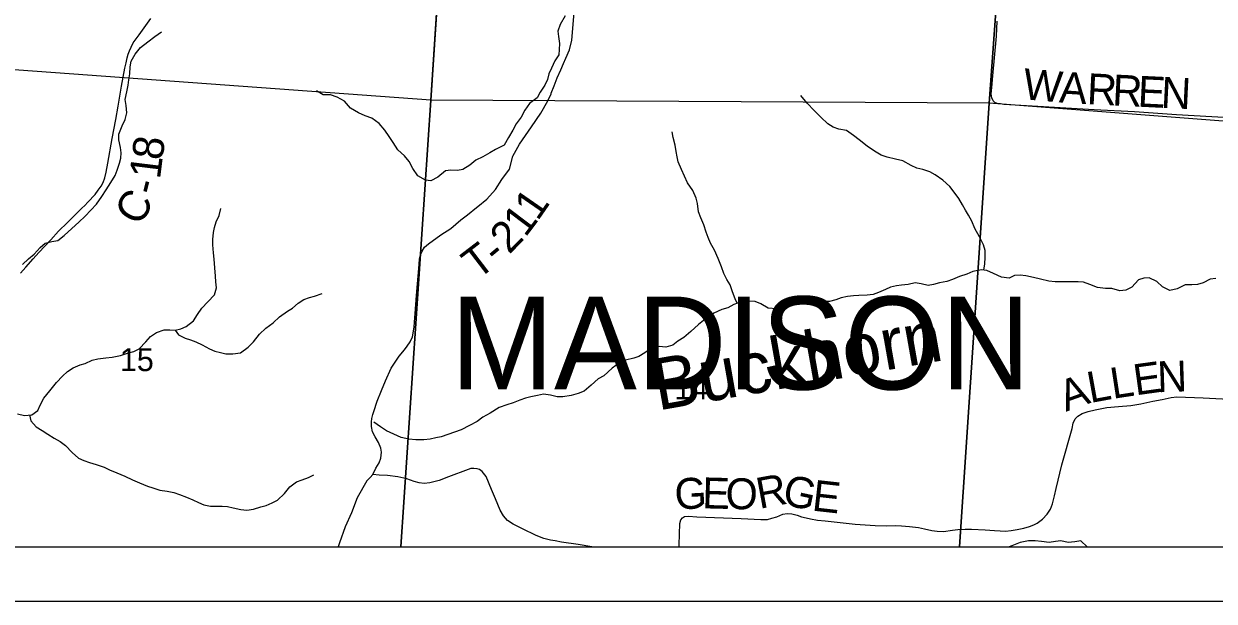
# Model space of a CAD drawing. Extents: x 0 to 40.8, y 0 to 22.
# Drawn here: x 5.517 to 7.699, y 14 to 15.059 of the extents above; entities that cross this region are included whole.
import ezdxf

# ---------------------------------------------------------------- set-up
doc = ezdxf.new("R2010")
doc.units = 0
for name, color, linetype in [('Default', 7, 'Continuous'), ('GM_X_County_Road', 7, 'Continuous'), ('GM_X_County_Road_Text', 7, 'Continuous'), ('GM_X_Minor_River', 7, 'Continuous'), ('GM_X_Minor_River_Text', 7, 'Continuous'), ('GM_X_Section', 7, 'Continuous'), ('GM_X_Section_Text', 7, 'Continuous'), ('GM_X_Township_Road', 7, 'Continuous'), ('GM_X_Township_Road_Text', 7, 'Continuous'), ('GM_X_Township_Text', 7, 'Continuous'), ('SH_Cut_Line', 7, 'Continuous'), ('SH_Data', 7, 'Continuous')]:
    doc.layers.add(name, color=color, linetype=linetype)

msp = doc.modelspace()

# ---------------------------------------------------------------- linework, layer by layer
at = {"layer": 'Default'}
msp.add_lwpolyline([(2.1, 16.4387), (2.1, 14.1), (8.9, 14.1), (8.9, 16.9831), (7.7161, 17.0658), (7.7144, 17.066), (7.54, 17.0745), (7.4495, 17.0841), (6.9172, 17.1197), (6.1785, 17.166), (5.6278, 17.197), (5.3407, 17.2146), (4.8294, 17.2493), (4.5348, 17.2687), (3.4481, 17.3334), (3.1244, 17.3534), (2.8484, 17.3691), (2.8463, 17.3693), (2.4594, 17.3966), (2.4379, 17.0913), (2.3911, 16.4258)], close=True, dxfattribs=at)
at = {"layer": 'GM_X_County_Road'}
for points in [[(5.511, 14.6017), (5.5206, 14.6128), (5.5339, 14.6281), (5.5443, 14.6398), (5.5662, 14.6632), (5.5807, 14.6792), (5.5969, 14.695), (5.6142, 14.7123), (5.6234, 14.7209), (5.6287, 14.726), (5.6341, 14.7319), (5.6478, 14.7461), (5.6534, 14.754), (5.6587, 14.7614), (5.6623, 14.7685), (5.6653, 14.7769), (5.6676, 14.7871), (5.6709, 14.8036), (5.6788, 14.8491), (5.6854, 14.884), (5.69, 14.9081), (5.6961, 14.945), (5.7022, 14.9783), (5.7044, 14.9879), (5.7063, 14.9971), (5.7083, 15.004), (5.7106, 15.0098), (5.7139, 15.0167), (5.7177, 15.0243), (5.7228, 15.0317), (5.7287, 15.0393), (5.7498, 15.0691)], [(6.5583, 14.1), (6.5333, 14.1041), (6.5028, 14.1081), (6.4909, 14.1105), (6.4827, 14.112), (6.4703, 14.1152), (6.4562, 14.1208), (6.4315, 14.133), (6.4141, 14.1412), (6.4037, 14.1481), (6.3966, 14.1564), (6.3903, 14.1673), (6.3819, 14.1876), (6.3745, 14.2049), (6.3648, 14.2286), (6.3572, 14.238), (6.3527, 14.2417), (6.3479, 14.243), (6.3423, 14.2438), (6.3367, 14.2433), (6.3315, 14.2419), (6.2956, 14.2285), (6.2787, 14.2216), (6.2612, 14.2171), (6.2507, 14.2158), (6.2415, 14.217), (6.2326, 14.2194), (6.2191, 14.2245), (6.2024, 14.2285), (6.1835, 14.2305), (6.1686, 14.231), (6.1566, 14.2328), (6.1519, 14.227), (6.1459, 14.2209), (6.128, 14.1896), (6.1175, 14.1624), (6.106, 14.1363), (6.0956, 14.1074), (6.093, 14.1)]]:
    msp.add_lwpolyline(points, dxfattribs=at)
for points in [[(5.1921, 14.1), (6.208, 14.1), (6.2633, 14.9194), (5.2555, 14.9926)], [(6.208, 14.1), (7.2324, 14.1), (7.2868, 14.9136), (6.2633, 14.9194)], [(7.2324, 14.1), (8.213, 14.1), (8.2617, 14.8595), (7.7715, 14.8766), (7.2868, 14.9136)]]:
    msp.add_lwpolyline(points, close=True, dxfattribs=at)
at = {"layer": 'GM_X_Minor_River'}
for points in [[(6.5093, 15.0742), (6.5001, 15.0582), (6.4959, 15.0457), (6.4974, 15.0362), (6.4989, 15.0233), (6.4985, 15.0123), (6.4978, 15.0028), (6.4905, 14.9915), (6.4845, 14.9778), (6.4795, 14.9676), (6.4772, 14.9573), (6.4723, 14.9467), (6.4636, 14.9342), (6.4582, 14.9236), (6.4442, 14.9134), (6.4358, 14.9009), (6.429, 14.8884), (6.4199, 14.8762), (6.4134, 14.8641), (6.4054, 14.8508), (6.3978, 14.8368), (6.3819, 14.8289), (6.3713, 14.8228), (6.3588, 14.8152), (6.3459, 14.8092), (6.3349, 14.8001), (6.322, 14.7922), (6.3118, 14.7903), (6.2996, 14.7907), (6.2902, 14.7895), (6.2761, 14.7778), (6.2632, 14.7714), (6.2534, 14.7725), (6.2394, 14.7805), (6.2299, 14.7942), (6.2235, 14.8067), (6.2152, 14.8174), (6.2027, 14.828), (6.1944, 14.8417), (6.1868, 14.8527), (6.1789, 14.8645), (6.1683, 14.8766), (6.1547, 14.8862), (6.143, 14.8903), (6.1305, 14.8964), (6.1161, 14.9044), (6.1047, 14.9177), (6.0915, 14.925), (6.0794, 14.9292), (6.0657, 14.9292), (6.0536, 14.9364)], [(5.5144, 14.6177), (5.5257, 14.6283), (5.5356, 14.637), (5.5466, 14.6492), (5.556, 14.6571), (5.5682, 14.6598), (5.5792, 14.6621), (5.5909, 14.6708), (5.6049, 14.6841), (5.6178, 14.6954), (5.6292, 14.7064), (5.6398, 14.7178), (5.65, 14.7288), (5.6602, 14.7425), (5.6682, 14.755), (5.6765, 14.7683), (5.6841, 14.7812), (5.6883, 14.7911), (5.6925, 14.8036), (5.6947, 14.8131), (5.6955, 14.8229), (5.694, 14.8328), (5.691, 14.8465), (5.6913, 14.8567), (5.697, 14.8723), (5.7027, 14.884), (5.7057, 14.8958), (5.7046, 14.9098), (5.7027, 14.9208), (5.7057, 14.9349), (5.7084, 14.947), (5.7095, 14.9565), (5.7111, 14.9675), (5.7122, 14.9804), (5.7137, 14.9906), (5.7209, 15.0035), (5.7311, 15.016), (5.744, 15.0263), (5.7569, 15.0362), (5.7694, 15.0445)], [(7.2772, 14.6074), (7.2787, 14.6191), (7.2795, 14.6305), (7.2795, 14.6434), (7.2768, 14.6536), (7.2693, 14.6684), (7.2606, 14.684), (7.2553, 14.6973), (7.2489, 14.7083), (7.2432, 14.7178), (7.2379, 14.7273), (7.2311, 14.7387), (7.2247, 14.7482), (7.2145, 14.7611), (7.202, 14.7725), (7.188, 14.7824), (7.1778, 14.7877), (7.1653, 14.7923), (7.154, 14.7946), (7.1441, 14.7995), (7.1286, 14.8079), (7.115, 14.811), (7.0998, 14.8148), (7.0888, 14.8186), (7.0767, 14.8255), (7.0635, 14.835), (7.0487, 14.8467), (7.0381, 14.8544), (7.0253, 14.8639), (7.0113, 14.8662), (7.001, 14.8696), (6.9912, 14.8761), (6.9783, 14.8882), (6.9662, 14.9004), (6.9534, 14.9141), (6.9417, 14.9277)], [(6.8248, 14.5466), (6.8209, 14.5546), (6.8164, 14.5678), (6.8119, 14.5807), (6.8062, 14.5902), (6.8005, 14.6013), (6.796, 14.6134), (6.79, 14.629), (6.7832, 14.6442), (6.776, 14.6571), (6.7719, 14.6673), (6.7677, 14.6772), (6.7636, 14.6905), (6.7583, 14.7034), (6.7538, 14.7144), (6.7523, 14.73), (6.7496, 14.7398), (6.7436, 14.7539), (6.7338, 14.7679), (6.7281, 14.7801), (6.7228, 14.7923), (6.7164, 14.8059), (6.7149, 14.8154), (6.713, 14.8249), (6.7112, 14.8367), (6.7078, 14.8507), (6.7055, 14.861)], [(5.5056, 14.3441), (5.5181, 14.3407), (5.5318, 14.3422), (5.5427, 14.3502), (5.5469, 14.3597), (5.5534, 14.3726), (5.5647, 14.3862), (5.5768, 14.401), (5.5878, 14.4128), (5.5973, 14.4215), (5.6075, 14.4283), (5.62, 14.4336), (5.6295, 14.4363), (5.6424, 14.442), (5.6526, 14.4446), (5.667, 14.4465), (5.6788, 14.4477), (5.6943, 14.4511), (5.7068, 14.4549), (5.7186, 14.4579), (5.7284, 14.4632), (5.7405, 14.4761), (5.7489, 14.4856), (5.7602, 14.4932), (5.7743, 14.4977), (5.7845, 14.4977), (5.7947, 14.4974), (5.8049, 14.5), (5.8148, 14.5042), (5.8281, 14.5144), (5.8353, 14.5258), (5.8432, 14.5379), (5.8542, 14.5493), (5.8663, 14.5622), (5.8701, 14.5747), (5.869, 14.5861), (5.8682, 14.5964), (5.8671, 14.6119), (5.866, 14.6279), (5.8648, 14.6393), (5.8637, 14.6541), (5.8637, 14.6635), (5.8648, 14.6764), (5.8667, 14.6859), (5.8694, 14.6958), (5.8751, 14.7079), (5.8781, 14.7205)], [(7.7026, 14.5919), (7.6923, 14.5911), (7.6791, 14.5843), (7.6688, 14.5809), (7.6582, 14.5805), (7.6465, 14.5806), (7.6313, 14.573), (7.618, 14.5704), (7.6048, 14.5768), (7.5946, 14.5867), (7.5802, 14.5932), (7.5707, 14.5928), (7.5609, 14.5898), (7.5487, 14.5765), (7.5377, 14.5705), (7.5264, 14.5694), (7.5116, 14.5736), (7.4999, 14.574), (7.4858, 14.5759), (7.4715, 14.5812), (7.4597, 14.5854), (7.4499, 14.5858), (7.4374, 14.5862), (7.4222, 14.5859), (7.4082, 14.5859), (7.3964, 14.5874), (7.3813, 14.5909), (7.3684, 14.5939), (7.3544, 14.597), (7.3438, 14.5985), (7.3336, 14.5974), (7.3233, 14.5928), (7.3093, 14.5944), (7.2949, 14.6012), (7.2828, 14.6066), (7.2726, 14.6081), (7.2571, 14.6051), (7.2461, 14.6002), (7.2328, 14.5956), (7.2199, 14.5903), (7.2093, 14.5866), (7.1957, 14.5839), (7.1847, 14.5809), (7.1748, 14.5794), (7.1623, 14.5821), (7.1513, 14.584), (7.1381, 14.5814), (7.1263, 14.5799), (7.1168, 14.5787), (7.1062, 14.5761), (7.0968, 14.5719), (7.0842, 14.5663), (7.074, 14.5629), (7.063, 14.5614), (7.0479, 14.561), (7.0384, 14.5603), (7.0274, 14.5592), (7.0153, 14.5565), (7.0058, 14.5527), (6.994, 14.5501), (6.9846, 14.5501), (6.9747, 14.5509), (6.9626, 14.552), (6.9524, 14.5517), (6.9425, 14.5513), (6.9281, 14.5506), (6.9187, 14.5483), (6.9084, 14.5434), (6.8967, 14.5366), (6.8815, 14.5374), (6.8683, 14.5454), (6.858, 14.5499), (6.8417, 14.5507), (6.8319, 14.5492), (6.8186, 14.5443), (6.8076, 14.5383), (6.797, 14.5352), (6.7822, 14.5284), (6.7727, 14.5216), (6.7633, 14.5152), (6.7538, 14.508), (6.7397, 14.4947), (6.7268, 14.4841), (6.7162, 14.4773), (6.7067, 14.4701), (6.6939, 14.466), (6.6821, 14.4675), (6.6688, 14.4656), (6.6556, 14.4558), (6.6446, 14.4493), (6.6351, 14.4459), (6.6203, 14.4422), (6.6089, 14.4373), (6.5957, 14.4274), (6.5805, 14.4138), (6.5699, 14.4081), (6.5573, 14.3964), (6.5441, 14.3854), (6.5331, 14.3812), (6.5202, 14.3774)], [(5.7947, 14.4974), (5.8008, 14.489), (5.8129, 14.4829), (5.8224, 14.4795), (5.8326, 14.4757), (5.844, 14.4704), (5.8572, 14.4628), (5.8674, 14.459), (5.8777, 14.4564), (5.8871, 14.4541), (5.9004, 14.4537), (5.914, 14.456), (5.9284, 14.4662), (5.9379, 14.4757), (5.9489, 14.4897), (5.9607, 14.5011), (5.9739, 14.5106), (5.986, 14.522), (6.0001, 14.5319), (6.0095, 14.5379), (6.0201, 14.547), (6.0304, 14.5535), (6.0406, 14.5573), (6.0501, 14.5595), (6.0637, 14.5649)], [(6.5202, 14.3774), (6.5054, 14.3748), (6.4948, 14.3752), (6.4827, 14.3783), (6.4698, 14.3798), (6.4588, 14.3775), (6.4467, 14.3753), (6.4365, 14.3723), (6.4262, 14.3689), (6.4141, 14.364), (6.4023, 14.3602), (6.3883, 14.3553), (6.372, 14.3451), (6.3587, 14.3375), (6.3481, 14.3299), (6.3341, 14.3227), (6.3189, 14.3144), (6.3064, 14.3103), (6.2943, 14.3057), (6.2821, 14.3019), (6.2723, 14.2997), (6.2617, 14.2974), (6.2503, 14.2963), (6.2359, 14.2963), (6.223, 14.2971), (6.209, 14.3002), (6.1954, 14.3063), (6.1821, 14.3127), (6.1708, 14.32), (6.1587, 14.3287)], [(5.5276, 14.3417), (5.5295, 14.3312), (5.5397, 14.3198), (5.5503, 14.313), (5.5609, 14.3065), (5.5727, 14.2989), (5.5833, 14.2932), (5.5935, 14.286), (5.6056, 14.2731), (5.6174, 14.2625), (5.6268, 14.2579), (5.6371, 14.2545), (5.6496, 14.2511), (5.664, 14.2458), (5.6742, 14.2412), (5.6875, 14.2356), (5.7019, 14.2295), (5.7159, 14.223), (5.7291, 14.2173), (5.7439, 14.2113), (5.7534, 14.2082), (5.7666, 14.2037), (5.7799, 14.2018), (5.792, 14.1995), (5.8022, 14.1961), (5.8151, 14.1911), (5.8269, 14.1862), (5.8371, 14.1813), (5.8469, 14.1767), (5.8591, 14.1741), (5.8701, 14.1741), (5.8803, 14.1741), (5.8905, 14.1737), (5.9007, 14.1714), (5.9151, 14.168), (5.9257, 14.1672), (5.9383, 14.1691), (5.9515, 14.1733), (5.961, 14.1759), (5.9724, 14.1805), (5.9818, 14.1854), (5.9947, 14.1979), (6.0046, 14.2101), (6.0171, 14.2192), (6.0273, 14.2226), (6.039, 14.2268), (6.0485, 14.2321)], [(7.4665, 14.1), (7.4547, 14.1107), (7.4441, 14.1092), (7.4316, 14.1077), (7.4184, 14.1108), (7.4085, 14.1093), (7.3971, 14.1078), (7.3827, 14.1093), (7.3714, 14.1105), (7.3593, 14.1105), (7.3437, 14.1079), (7.3282, 14.1018), (7.3237, 14.1)]]:
    msp.add_lwpolyline(points, dxfattribs=at)
at = {"layer": 'GM_X_Section'}
for points in [[(6.3112, 15.6512), (6.2633, 14.9194), (5.2555, 14.9926), (5.3264, 16.0026), (5.5999, 15.9856)], [(7.079, 15.9397), (7.3612, 15.9396), (7.2868, 14.9136), (6.2633, 14.9194), (6.311, 15.6491)]]:
    msp.add_lwpolyline(points, dxfattribs=at)
msp.add_lwpolyline([(8.344, 15.8695), (8.2661, 14.9102), (8.2617, 14.8595), (7.7715, 14.8766), (7.2868, 14.9136), (7.3612, 15.9396)], close=True, dxfattribs=at)
at = {"layer": 'GM_X_Township_Road'}
for points in [[(6.4841, 14.9319), (6.4894, 14.9455), (6.495, 14.9605), (6.5013, 14.9753), (6.5064, 14.9864), (6.5105, 14.9966), (6.5173, 15.0119), (6.5217, 15.0297), (6.5255, 15.0727), (6.5308, 15.122), (6.5364, 15.1668), (6.5377, 15.178)], [(7.7276, 14.8872), (7.6304, 14.8923), (7.5534, 14.8977), (7.4796, 14.9017), (7.314, 14.9116), (7.3074, 14.9124), (7.3016, 14.9134), (7.297, 14.9149), (7.2942, 14.918), (7.2919, 14.9236), (7.2906, 14.9305), (7.2922, 14.9495), (7.2939, 14.9643), (7.3003, 15.037), (7.3013, 15.0642)], [(6.3472, 14.7224), (6.3495, 14.7242), (6.3658, 14.738), (6.3818, 14.7555), (6.3935, 14.7737), (6.4072, 14.7929), (6.4138, 14.8168), (6.4255, 14.8389), (6.4479, 14.8702), (6.4647, 14.8957), (6.4779, 14.9183), (6.4838, 14.931), (6.4841, 14.9319)], [(6.1566, 14.2328), (6.1625, 14.2439), (6.1687, 14.2537), (6.1717, 14.2624), (6.1727, 14.2733), (6.1712, 14.281), (6.1671, 14.2911), (6.161, 14.3016), (6.1565, 14.3107), (6.1542, 14.3204), (6.1542, 14.3293), (6.1547, 14.3354), (6.157, 14.3428), (6.1585, 14.3478), (6.1648, 14.3669), (6.1727, 14.3864), (6.1798, 14.4046), (6.1902, 14.4278), (6.2053, 14.4496), (6.2152, 14.4613), (6.2198, 14.4679), (6.2251, 14.4758), (6.2297, 14.4852), (6.2307, 14.492), (6.2327, 14.5035), (6.2368, 14.5612), (6.2416, 14.6179), (6.2427, 14.6281), (6.2444, 14.6357), (6.2474, 14.6424), (6.2518, 14.6495), (6.2589, 14.6558), (6.2813, 14.6721), (6.2999, 14.6841), (6.3182, 14.6996), (6.3302, 14.7092), (6.3472, 14.7224)], [(6.7184, 14.1), (6.7185, 14.1036), (6.7199, 14.1426), (6.7217, 14.1492), (6.7245, 14.1527), (6.7283, 14.1555), (6.7354, 14.1563), (6.7507, 14.1548), (6.8321, 14.1515), (6.8682, 14.1497), (6.8802, 14.1502), (6.8886, 14.1522), (6.8975, 14.155), (6.9084, 14.1596), (6.9168, 14.1611), (6.9252, 14.1601), (6.9346, 14.1576), (6.9427, 14.1548), (6.9514, 14.1527), (6.959, 14.151), (6.9722, 14.1489), (6.986, 14.1476), (7.0409, 14.1413), (7.078, 14.139), (7.0981, 14.1382), (7.1149, 14.1387), (7.1261, 14.1385), (7.1411, 14.1372), (7.1576, 14.1354), (7.1681, 14.1329), (7.1815, 14.1296), (7.1915, 14.1283), (7.2029, 14.1281), (7.2197, 14.1301), (7.2296, 14.1316), (7.2426, 14.1324), (7.2543, 14.1319), (7.2797, 14.1311), (7.2965, 14.1298), (7.3069, 14.1293), (7.3171, 14.1288), (7.3273, 14.1298), (7.3385, 14.1316), (7.3502, 14.1339), (7.3606, 14.137), (7.3687, 14.14), (7.3748, 14.1433), (7.3845, 14.1504), (7.3934, 14.1596), (7.3995, 14.1688), (7.4031, 14.1789), (7.4066, 14.1934), (7.4097, 14.2066), (7.4203, 14.2501), (7.4389, 14.3168), (7.4412, 14.3269), (7.4448, 14.3346), (7.4493, 14.3394), (7.4572, 14.3442), (7.4682, 14.3483), (7.4814, 14.3511), (7.5025, 14.3554), (7.5239, 14.357), (7.5465, 14.359), (7.5648, 14.362), (7.5867, 14.3671), (7.6042, 14.3704), (7.6208, 14.374), (7.6309, 14.375), (7.6793, 14.3732), (7.738, 14.3699)]]:
    msp.add_lwpolyline(points, dxfattribs=at)
at = {"layer": 'SH_Cut_Line'}
msp.add_lwpolyline([(2.1, 17.4153), (2.1, 14.1), (8.9, 14.1), (8.9, 16.9831), (7.7161, 17.0658), (7.7144, 17.066), (7.54, 17.0745), (7.4495, 17.0841), (6.9172, 17.1197), (6.1785, 17.166), (5.6278, 17.197), (5.3407, 17.2146), (4.8294, 17.2493), (4.5348, 17.2687), (3.4481, 17.3334), (3.1244, 17.3534), (2.8484, 17.3691), (2.8463, 17.3693), (2.4594, 17.3966)], close=True, dxfattribs=at)
at = {"layer": 'SH_Data'}
for p, q in [((2.1, 14.1), (8.9, 14.1)), ((2, 14), (9, 14))]:
    msp.add_line(p, q, dxfattribs=at)

# ---------------------------------------------------------------- texts
at = {"layer": 'GM_X_County_Road_Text'}
for s, rotation, p in [('8', 82.558, (5.7709, 14.8077)), ('1', 83.0003, (5.7666, 14.7731)), ('-', 76.2276, (5.7597, 14.7432)), ('C', 59.3803, (5.7291, 14.6862))]:
    msp.add_text(s, height=0.0568, rotation=rotation, dxfattribs=at).set_placement(p)
at = {"layer": 'GM_X_Minor_River_Text'}
msp.add_text('Buckhorn', height=0.09469, rotation=10.0043, dxfattribs=at).set_placement((6.6792, 14.3496))
at = {"layer": 'GM_X_Section_Text'}
for s, p in [('15', (5.693, 14.4222)), ('14', (6.7096, 14.3703))]:
    msp.add_text(s, height=0.04186, rotation=0, dxfattribs=at).set_placement(p)
at = {"layer": 'GM_X_Township_Road_Text'}
for s, rotation, p in [('W', 354.8832, (7.3472, 14.9213)), ('A', 356.3069, (7.4143, 14.9153)), ('R', 357.2005, (7.4652, 14.9121)), ('R', 357.2413, (7.5118, 14.9098)), ('E', 357.2457, (7.5584, 14.9075)), ('N', 357.2413, (7.6009, 14.9055)), ('1', 55.3287, (6.459, 14.6962)), ('1', 52.8735, (6.4364, 14.6662)), ('2', 45.5826, (6.4067, 14.6352)), ('T', 37.469, (6.3485, 14.5886)), ('-', 39.8125, (6.3842, 14.6161)), ('L', 8.6944, (7.5135, 14.3712)), ('E', 7.8677, (7.5553, 14.3776)), ('N', 1.9164, (7.5958, 14.3833)), ('A', 19.7114, (7.4274, 14.3474)), ('L', 10.3324, (7.4721, 14.3636)), ('R', 10.4651, (6.8656, 14.1693)), ('G', 347.937, (6.9056, 14.1779)), ('G', 3.0505, (6.7115, 14.1679)), ('E', 358.5213, (6.7603, 14.1705)), ('O', 358.7388, (6.803, 14.1694)), ('E', 353.6141, (6.9606, 14.1665))]:
    msp.add_text(s, height=0.0568, rotation=rotation, dxfattribs=at).set_placement(p)
at = {"layer": 'GM_X_Township_Text'}
msp.add_text('MADISON', height=0.17045, rotation=0, dxfattribs=at).set_placement((6.2991, 14.3885))

doc.saveas('drawing.dxf')
